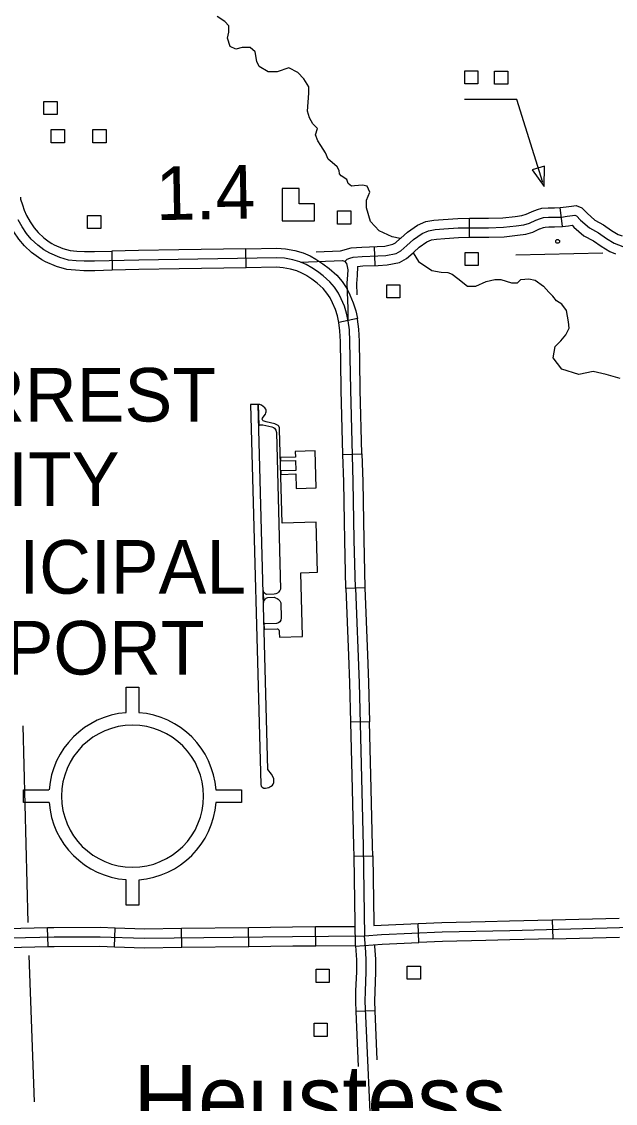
# Model space of a CAD drawing. Extents: x 155 to 3386, y 68 to 2138.
# Drawn here: x 1722.1 to 1855.9, y 551.2 to 794.9 of the extents above; entities that cross this region are included whole.
import ezdxf

# ---------------------------------------------------------------- set-up
doc = ezdxf.new("R2010")
doc.units = 0
for name, color, linetype in [('Level 24', 7, 'Continuous'), ('Level 31', 7, 'Continuous'), ('Level 32', 7, 'Continuous'), ('Level 35', 7, 'Continuous'), ('Level 43', 7, 'Continuous'), ('Level 45', 7, 'Continuous'), ('Level 48', 7, 'Continuous'), ('Level 5', 7, 'Continuous'), ('Level 56', 7, 'Continuous'), ('Level 57', 7, 'Continuous'), ('Level 58', 7, 'Continuous')]:
    doc.layers.add(name, color=color, linetype=linetype)

msp = doc.modelspace()

# ---------------------------------------------------------------- linework, layer by layer
at = {"layer": 'Level 31'}
for p, q in [((1772.69, 739.48), (1772.62, 743.76)), ((1742.43, 743.21), (1742.54, 738.93)), ((1786.29, 737.71), (1786.29, 737.71)), ((1797.77, 728.08), (1793.59, 727.15)), ((1794.5, 697.41), (1798.79, 697.53)), ((1799.45, 667.39), (1795.17, 667.22)), ((1800.51, 637.21), (1796.23, 637.1)), ((1796.95, 606.96), (1801.23, 607.03)), ((1841.65, 592.59), (1841.76, 588.31)), ((1811.64, 587.5), (1811.45, 591.78))]:
    msp.add_line(p, q, dxfattribs=at)
for points in [[(1726.69, 741.29), (1725.92, 741.76), (1724.36, 742.95), (1722.74, 744.44), (1721.47, 745.95), (1720.4, 747.61), (1719.39, 749.34), (1718.72, 750.94), (1718.24, 752.27), (1717.63, 754.21), (1717.59, 755.22)], [(1721.87, 755.4), (1721.89, 754.96), (1722.31, 753.64), (1722.72, 752.49), (1723.23, 751.25), (1724.05, 749.85), (1724.92, 748.5), (1725.84, 747.41), (1727.12, 746.24), (1728.33, 745.31), (1728.9, 744.97)], [(1797.31, 667.31), (1797.05, 678.2), (1796.81, 691.3), (1796.25, 711.98), (1796.07, 722.9), (1795.97, 725.49), (1795.7, 727.52), (1795.32, 729.24), (1794.82, 730.8), (1794.11, 732.49), (1793.49, 733.76), (1792.6, 735.09), (1791.57, 736.3), (1790.06, 737.66), (1788.74, 738.63), (1787.5, 739.49), (1786.2, 740.22), (1784.81, 740.79), (1783.19, 741.26), (1781.33, 741.61), (1779.58, 741.73), (1748.5, 741.23), (1738.55, 740.96), (1736.22, 740.96), (1734.39, 741.05), (1732.67, 741.23), (1730.7, 741.79), (1728.45, 742.74), (1727.12, 743.53), (1725.74, 744.6), (1724.29, 745.93), (1723.2, 747.22), (1722.22, 748.73), (1721.31, 750.3)], [(1728.9, 744.97), (1729.43, 744.65), (1731.41, 743.82), (1733.08, 743.34), (1734.55, 743.19), (1736.27, 743.11), (1738.52, 743.11), (1742.43, 743.21)], [(1757.54, 743.52), (1748.45, 743.37), (1742.43, 743.21)], [(1772.62, 743.76), (1757.54, 743.52)], [(1772.62, 743.76), (1779.64, 743.88), (1781.6, 743.74), (1783.69, 743.34), (1785.51, 742.81), (1787.13, 742.16), (1788.41, 741.43)], [(1742.54, 738.93), (1738.58, 738.82), (1736.17, 738.82), (1734.22, 738.91), (1732.27, 739.12), (1729.99, 739.76), (1727.48, 740.82), (1726.69, 741.29)], [(1788.41, 741.43), (1788.64, 741.3), (1789.98, 740.38), (1791.42, 739.32), (1793.11, 737.79), (1794.32, 736.38), (1795.35, 734.83), (1796.06, 733.37), (1796.83, 731.55), (1797.39, 729.8), (1797.77, 728.08)], [(1757.6, 739.23), (1748.54, 739.09), (1742.54, 738.93)], [(1772.69, 739.48), (1757.6, 739.23)], [(1786.29, 737.71), (1785.26, 738.29), (1784.11, 738.76), (1782.68, 739.17), (1781.05, 739.48), (1779.53, 739.59), (1772.69, 739.48)], [(1793.59, 727.15), (1793.25, 728.67), (1792.81, 730.06), (1792.16, 731.6), (1791.63, 732.69), (1790.89, 733.79), (1790.03, 734.8), (1788.71, 735.99), (1787.49, 736.88), (1786.35, 737.67), (1786.29, 737.71)], [(1794.1, 712.52), (1793.93, 722.84), (1793.83, 725.3), (1793.59, 727.15), (1793.59, 727.15)], [(1798.38, 712.59), (1798.22, 722.97), (1798.11, 725.67), (1797.81, 727.9), (1797.77, 728.08)], [(1794.5, 697.41), (1794.11, 711.93), (1794.1, 712.52)], [(1798.79, 697.53), (1798.39, 712.02), (1798.38, 712.59)], [(1794.83, 682.35), (1794.67, 691.25), (1794.5, 697.41)], [(1798.79, 697.53), (1798.95, 691.35), (1799.12, 682.43)], [(1795.17, 667.22), (1794.91, 678.15), (1794.83, 682.35)], [(1799.12, 682.43), (1799.19, 678.24), (1799.45, 667.39)], [(1795.17, 667.22), (1795.77, 652.15)], [(1797.31, 667.31), (1798.16, 646.01), (1799.06, 609.19), (1799.39, 589), (1803.2, 589.28), (1816.86, 589.87), (1832.07, 590.19), (1878.76, 591.43), (1910.14, 592.71), (1924.39, 593.22), (1929.89, 593.26), (1956.37, 594.32), (1957.8, 594.37)], [(1799.45, 667.39), (1800.05, 652.32)], [(1795.77, 652.15), (1796.01, 645.94), (1796.23, 637.1)], [(1800.05, 652.32), (1800.3, 646.08), (1800.51, 637.21)], [(1796.23, 637.1), (1796.6, 622.02)], [(1800.88, 622.13), (1800.51, 637.21)], [(1796.6, 622.02), (1796.91, 609.15), (1796.95, 606.96)], [(1801.23, 607.03), (1801.2, 609.24), (1800.88, 622.13)], [(1796.95, 606.96), (1797.2, 591.87)], [(1801.23, 607.03), (1801.49, 591.94)], [(1811.45, 591.78), (1816.79, 592.01), (1826.58, 592.22)], [(1826.58, 592.22), (1832.02, 592.33), (1841.65, 592.59)], [(1841.65, 592.59), (1856.73, 592.99)], [(1797.2, 591.87), (1797.29, 586.69), (1803.33, 587.14), (1811.64, 587.5)], [(1801.49, 591.94), (1801.5, 591.3), (1803.08, 591.41), (1811.45, 591.78)], [(1826.67, 587.93), (1816.92, 587.73), (1811.64, 587.5)], [(1841.76, 588.31), (1832.12, 588.05), (1826.67, 587.93)], [(1841.76, 588.31), (1856.84, 588.71)]]:
    msp.add_lwpolyline(points, dxfattribs=at)
at = {"layer": 'Level 32'}
for p, q in [((1823.05, 746.34), (1823.03, 750.63)), ((1801.78, 739.99), (1801.61, 744.27)), ((1728.08, 586.55), (1727.98, 590.84)), ((1743.04, 586.52), (1743.18, 590.81)), ((1758.22, 586.41), (1758.17, 590.7)), ((1773.3, 586.6), (1773.25, 590.88)), ((1788.38, 586.76), (1788.34, 591.05)), ((1801.77, 572.09), (1797.49, 571.91))]:
    msp.add_line(p, q, dxfattribs=at)
for points in [[(1836.99, 752.1), (1837.14, 752.17), (1838.34, 752.64), (1839.31, 752.9), (1840.75, 753.01), (1842.13, 753.01), (1843.43, 753.05)], [(1794.93, 740.88), (1795.45, 741.4), (1796.07, 741.67), (1796.78, 741.89), (1798.87, 742.02), (1802.34, 742.16), (1804.2, 742.25), (1806.51, 742.73), (1807.58, 743.31), (1808.87, 744.47), (1810.38, 745.85), (1812.33, 747.18), (1813.8, 747.8), (1815.27, 748.07), (1817.26, 748.25), (1820.44, 748.47), (1827.32, 748.51), (1830.66, 748.6), (1833.54, 748.91), (1835.28, 749.18), (1836.57, 749.54), (1837.99, 750.2), (1839.01, 750.6), (1839.68, 750.78), (1840.83, 750.87), (1842.16, 750.87), (1843.72, 750.91)], [(1807.57, 746.18), (1809.05, 747.53), (1811.3, 749.07), (1813.18, 749.87), (1814.98, 750.19), (1817.09, 750.38), (1820.36, 750.61), (1823.03, 750.63)], [(1823.03, 750.63), (1827.29, 750.66), (1830.51, 750.74), (1833.27, 751.04), (1834.83, 751.28), (1835.82, 751.55), (1836.99, 752.1)], [(1823.05, 746.34), (1827.36, 746.37), (1830.8, 746.46), (1833.82, 746.79), (1835.73, 747.08), (1837.31, 747.52), (1838.81, 748.22)], [(1838.81, 748.22), (1838.83, 748.23), (1839.68, 748.56), (1840.04, 748.66), (1840.91, 748.73), (1842.19, 748.73), (1844, 748.78)], [(1793.99, 743.26), (1796.39, 744.01), (1798.76, 744.16), (1802.24, 744.3), (1803.93, 744.38), (1805.76, 744.77), (1806.34, 745.08), (1807.43, 746.06), (1807.57, 746.18)], [(1810.46, 743.02), (1811.71, 744.16), (1813.37, 745.29), (1814.42, 745.74), (1815.55, 745.94), (1817.43, 746.11), (1820.52, 746.33), (1823.05, 746.34)], [(1788.47, 743.04), (1793.99, 743.26)], [(1784.88, 740.76), (1794.43, 741.13), (1794.87, 740.96), (1795.32, 740.42), (1795.49, 739.8), (1795.58, 739), (1795.54, 737.89), (1795.4, 736.02), (1795.45, 734.02), (1795.63, 730.33), (1795.64, 727.82)], [(1797.76, 739.8), (1798.98, 739.88), (1802.43, 740.02), (1804.48, 740.11), (1807.26, 740.7), (1808.82, 741.55), (1810.3, 742.88), (1810.46, 743.02)], [(1797.76, 739.8), (1797.68, 737.77), (1797.55, 735.94)], [(1797.55, 735.97), (1797.61, 733.38)], [(1712.9, 590.5), (1727.98, 590.84)], [(1727.98, 590.84), (1729.41, 590.87), (1739.82, 590.91), (1743.18, 590.81)], [(1743.18, 590.81), (1749.8, 590.59), (1758.17, 590.7)], [(1758.17, 590.7), (1773.25, 590.88)], [(1773.25, 590.88), (1783.16, 591.01), (1788.34, 591.05)], [(1788.34, 591.05), (1797.21, 591.12)], [(1652.63, 586.62), (1684.39, 587.72), (1729.43, 588.73), (1739.79, 588.77), (1749.78, 588.45), (1783.18, 588.86), (1799.39, 589)], [(1806.14, 360.92), (1805.82, 392.28), (1805.24, 403.55), (1804.71, 429.41), (1803.39, 465.91), (1802.44, 502.56), (1801.06, 539.27), (1799.53, 574.23), (1799.58, 576.51), (1799.74, 580.84), (1799.74, 583.65), (1799.58, 586.5), (1799.39, 589)], [(1712.99, 586.21), (1728.08, 586.55)], [(1728.08, 586.55), (1729.46, 586.58), (1739.76, 586.63), (1743.04, 586.52)], [(1743.04, 586.52), (1749.76, 586.31), (1758.22, 586.41)], [(1758.22, 586.41), (1773.3, 586.6)], [(1773.3, 586.6), (1783.2, 586.72), (1788.38, 586.76)], [(1788.38, 586.76), (1797.29, 586.84)], [(1797.49, 571.91), (1797.39, 574.21), (1797.44, 576.57), (1797.6, 580.88), (1797.6, 583.59), (1797.43, 586.7)], [(1801.77, 572.09), (1801.67, 574.25), (1801.73, 576.44), (1801.89, 580.8), (1801.89, 583.71), (1801.72, 586.64), (1801.69, 587.02)], [(1798.03, 559.58), (1797.49, 571.91)], [(1802.25, 561.03), (1801.77, 572.09)]]:
    msp.add_lwpolyline(points, dxfattribs=at)
at = {"layer": 'Level 35'}
for points in [[(1807.43, 746.06), (1805.56, 746.47), (1802.65, 747.82), (1800.74, 749.94), (1799.82, 752.99), (1799.82, 754.72), (1800.54, 756.55), (1799.93, 757.87), (1798.91, 758.07), (1797.08, 757.97), (1796.47, 757.87), (1795.66, 758.48), (1795.35, 759.4), (1794.13, 760.21), (1793.72, 760.62), (1793.62, 761.43), (1793.22, 762.24), (1792.1, 763.16), (1791.18, 763.97), (1790.56, 765.36), (1789.54, 767.04), (1788.83, 768.06), (1788.34, 769.46), (1788.74, 770.89), (1787.73, 771.91), (1787, 773.25), (1786.49, 774.77), (1786.81, 778.82), (1786.81, 780.24), (1785.69, 782.08), (1784.37, 783.5), (1782.34, 784.52), (1779.7, 783.6), (1777.66, 783.6), (1775.63, 784.82), (1775.12, 785.94), (1774.72, 788.12), (1773.6, 789.13), (1771.77, 789.13), (1770.35, 788.73), (1769.13, 789.34), (1768.52, 791.17), (1768.82, 792.59), (1768.82, 794.02), (1767.91, 794.93)], [(1810.3, 742.88), (1811.51, 740.88), (1814.52, 738.87), (1816.61, 738.49), (1818.15, 738.41), (1819.08, 738.02), (1820.39, 737.1), (1822.55, 735.32), (1824.41, 735.32), (1826.8, 736.4), (1828.73, 736.87), (1830.04, 736.87), (1832.51, 736.09), (1833.83, 736.09), (1834.6, 736.87), (1836.38, 737.02), (1837.84, 736.71), (1839.69, 735.32), (1840.89, 733.97)], [(1853.83, 715.47), (1850.9, 716.11), (1847.62, 715.42), (1843.81, 716.63), (1841.88, 719.16), (1842.35, 721.71), (1843.63, 722.99), (1844.75, 724.41), (1845.5, 725.85), (1845.29, 727.28), (1844.89, 729.87), (1843.82, 731.3), (1842.63, 732), (1841.78, 733.08), (1840.89, 733.97)], [(1856.95, 714.55), (1853.83, 715.47)]]:
    msp.add_lwpolyline(points, dxfattribs=at)
at = {"layer": 'Level 43'}
msp.add_lwpolyline([(1767.91, 794.93), (1766.14, 796.05)], dxfattribs=at)
at = {"layer": 'Level 45'}
msp.add_line((1844, 748.79), (1843.44, 753.04), dxfattribs=at)
for points in [[(1843.44, 753.04), (1844.79, 753.22), (1845.96, 753.35), (1847.05, 753.53), (1848.34, 752.98), (1849.51, 751.76), (1851.26, 750.24), (1853.2, 749.18), (1855.03, 747.9), (1856.53, 746.98), (1857.39, 746.65)], [(1843.72, 750.91), (1845.05, 751.09), (1846.25, 751.22), (1846.78, 751.31), (1847.1, 751.18), (1848.03, 750.2), (1850.03, 748.47), (1852.07, 747.36), (1853.85, 746.11), (1855.58, 745.05), (1857.58, 744.29), (1860.38, 743.98), (1863.58, 743.89), (1865.58, 744.07), (1866.51, 744.07), (1867.71, 743.76), (1868.51, 743.49), (1869.84, 743.67), (1871.36, 744.2), (1871.8, 744.38)], [(1844, 748.79), (1845.31, 748.96), (1846.16, 749.06), (1846.55, 748.65), (1848.8, 746.7), (1850.94, 745.53), (1852.67, 744.32), (1854.63, 743.11), (1855.88, 742.64)]]:
    msp.add_lwpolyline(points, dxfattribs=at)
at = {"layer": 'Level 5'}
for points in [[(1833.49, 742.39), (1853.08, 742.86)], [(1722.37, 636.31), (1723.54, 591.99)], [(1723.78, 584.55), (1724.98, 551.56)]]:
    msp.add_lwpolyline(points, dxfattribs=at)
at = {"layer": 'Level 56'}
for points in [[(1821.93, 780.9), (1821.93, 783.87), (1824.92, 783.87), (1824.92, 780.9)], [(1828.65, 780.82), (1828.65, 783.8), (1831.63, 783.8), (1831.63, 780.82)], [(1727.16, 773.99), (1727.16, 776.97), (1730.15, 776.97), (1730.15, 773.99)], [(1728.79, 767.65), (1728.79, 770.62), (1731.78, 770.62), (1731.78, 767.65)], [(1738.18, 767.65), (1738.18, 770.62), (1741.17, 770.62), (1741.17, 767.65)], [(1839.93, 762.39), (1837.15, 761.51), (1839.85, 757.78)], [(1736.95, 748.3), (1736.95, 751.28), (1739.94, 751.28), (1739.94, 748.3)], [(1793.3, 749.3), (1793.3, 752.28), (1796.28, 752.28), (1796.28, 749.3)], [(1822.01, 739.96), (1822.01, 742.94), (1824.99, 742.94), (1824.99, 739.96)], [(1804.38, 732.69), (1804.38, 735.67), (1807.36, 735.67), (1807.36, 732.69)], [(1788.44, 578.48), (1788.44, 581.45), (1791.42, 581.45), (1791.42, 578.48)], [(1809, 579.19), (1809, 582.16), (1811.99, 582.16), (1811.99, 579.19)], [(1788, 566.3), (1788, 569.27), (1790.98, 569.27), (1790.98, 566.3)]]:
    msp.add_lwpolyline(points, close=True, dxfattribs=at)
msp.add_lwpolyline([(1839.54, 758.71), (1833.67, 777.4), (1821.86, 777.4)], dxfattribs=at)
at = {"layer": 'Level 57'}
for p, q in [((1745.68, 639.26), (1745.68, 645.01)), ((1745.68, 645.01), (1748.54, 645.01)), ((1748.54, 645.01), (1748.54, 639.26)), ((1722.54, 619.01), (1722.54, 621.87)), ((1722.54, 621.87), (1728.24, 621.87)), ((1765.89, 621.87), (1771.68, 621.87)), ((1771.68, 621.87), (1771.68, 619.01)), ((1728.29, 619.01), (1722.54, 619.01)), ((1771.68, 619.01), (1765.89, 619.01)), ((1745.68, 595.87), (1745.68, 601.56)), ((1748.54, 601.51), (1748.54, 595.87)), ((1748.54, 595.87), (1745.68, 595.87))]:
    msp.add_line(p, q, dxfattribs=at)
for points in [[(1775.4, 708.69), (1773.71, 708.65), (1775.98, 623.05)], [(1775.98, 623.05), (1776.07, 622.66), (1776.32, 622.44), (1776.71, 622.26), (1777.07, 622.24), (1777.46, 622.3), (1777.8, 622.39), (1778.07, 622.51), (1778.36, 622.69), (1778.63, 622.93), (1778.79, 623.16), (1778.9, 623.54), (1778.93, 623.91), (1778.9, 624.36), (1778.82, 624.7), (1778.41, 625.38), (1777.59, 626.47), (1775.4, 708.69)], [(1776.52, 666.77), (1776.59, 664.07), (1776.71, 664.43), (1776.81, 664.62), (1776.95, 664.8), (1777.06, 664.93), (1777.2, 665.04), (1777.35, 665.13), (1777.55, 665.2), (1779.03, 665.24), (1779.35, 665.14), (1779.67, 664.98), (1779.95, 664.79), (1780.26, 664.46), (1780.52, 664.03), (1780.62, 660.59), (1780.55, 660.06), (1780.32, 659.7), (1780, 659.49), (1779.51, 659.32), (1776.98, 659.25), (1776.89, 659.28), (1776.79, 659.38), (1776.74, 659.46), (1776.71, 659.58), (1776.75, 657.88), (1776.81, 657.99), (1776.87, 658.05), (1776.93, 658.08), (1779.67, 658.16), (1779.78, 658.13), (1779.9, 658.07), (1779.99, 657.98), (1780.06, 657.88), (1780.11, 657.7), (1780.14, 657.52), (1780.15, 657.3), (1780.18, 656.25), (1785.4, 656.39), (1785.02, 670.78), (1788.79, 670.88), (1788.49, 682.19), (1780.81, 681.98), (1780.25, 703.03), (1780.19, 703.45), (1780.03, 703.78), (1779.9, 703.96), (1779.64, 704.11), (1779.13, 704.32), (1777.19, 704.8), (1776.55, 704.98), (1776.43, 705.05), (1776.36, 705.2), (1776.33, 705.37), (1776.41, 705.6), (1776.75, 706.09), (1777.03, 706.53), (1777.13, 706.79), (1777.19, 707.02), (1777.22, 707.25), (1777.19, 707.44), (1777.11, 707.64), (1776.89, 707.93), (1776.52, 708.26), (1776.14, 708.5), (1775.96, 708.6), (1775.75, 708.67), (1775.4, 708.69), (1775.53, 703.95)], [(1775.53, 703.95), (1775.78, 704.07), (1776.04, 704.11), (1776.48, 704.09), (1778.52, 703.67), (1778.85, 703.5), (1779.11, 703.31), (1779.4, 702.87), (1779.51, 702.37), (1780.44, 667.05), (1780.28, 666.75), (1780.02, 666.4), (1779.73, 666.18), (1779.4, 666.03), (1779, 665.95), (1777.33, 665.91), (1777.14, 665.96), (1776.94, 666.1), (1776.81, 666.23), (1776.66, 666.42), (1776.6, 666.54), (1776.52, 666.77)], [(1788.51, 689.9), (1788.28, 698.23), (1783.75, 698.11), (1783.79, 696.83), (1780.42, 696.74), (1780.44, 695.96), (1783.81, 696.05), (1783.87, 693.83), (1780.5, 693.74), (1780.52, 692.94), (1783.89, 693.03), (1783.98, 689.78), (1788.51, 689.9)]]:
    msp.add_lwpolyline(points, dxfattribs=at)
msp.add_circle((1842.86, 745.42), 0.429, dxfattribs=at)
for radius, start, end in [(18.86, 94.3396, 175.6718), (18.86, 4.3511, 85.6603), (16, 0, 180), (18.86, 184.3396, 265.6718), (16, 180, 0), (18.86, 274.3169, 355.6489)]:
    msp.add_arc((1747.11, 620.44), radius, start, end, dxfattribs=at)
at = {"layer": 'Level 58'}
msp.add_lwpolyline([(1780.83, 750.09), (1788.09, 750.09), (1788.09, 753.92), (1784.66, 753.92), (1784.66, 757.35), (1780.83, 757.35)], close=True, dxfattribs=at)

# ---------------------------------------------------------------- texts
at = {"layer": 'Level 24'}
msp.add_text('Heustess', height=15.086, dxfattribs=at).set_placement((1747.29, 544.8))
at = {"layer": 'Level 48'}
msp.add_text('1.4', height=12.069, rotation=1.0176, dxfattribs=at).set_placement((1752.42, 750.2))
at = {"layer": 'Level 57'}
for s, p in [('FORREST', (1688.8, 704.84)), ('CITY', (1707.42, 685.83)), ('MUNICIPAL', (1684.83, 666.06)), ('AIRPORT', (1691.6, 647.85))]:
    msp.add_text(s, height=12.069, dxfattribs=at).set_placement(p)

doc.saveas('drawing.dxf')
